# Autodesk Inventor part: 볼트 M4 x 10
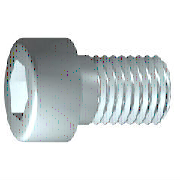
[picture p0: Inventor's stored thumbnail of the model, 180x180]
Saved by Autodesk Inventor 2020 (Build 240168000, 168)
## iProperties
Created: 2016-04
Part Number: 볼트 M4 x 10
Material: 강철, 연강
Description: 6각머리 태핑 나사
Document SubType Name: Modeling
Standard: KS B 1003
Designer: mdu
Standards Organization: KS
Language: ko-KR
Size Designation: M 4 x 10
Categories: <MemberInstance><Categories><Category DisplayName="조임쇠" InternalName="e4da775c-781d-43d5-af7c-5136215cf5a6" Mnemonic="FSTN"><Category DisplayName="볼트" InternalN
Density: 7.86 g/cm^3
Mass: 2.0371 g
Surface Area: 3.0572 cm^2
Volume: 0.259174 cm^3
Appearance: 강철
IsCustomPart: 0
Author: mdu
Revision Number: 1
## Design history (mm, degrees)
sketch "스케치1"
  geometry: L1 (-1, 0)-(10, 0); L2 (10, 0)-(10, 2); L3 (10, 2)-(1.75, 2); L4 (1.75, 2)-(1.32, 2); L5 (1.32, 2)-(0, 2); L6 (0, 2)-(0, 3.5); L7 (0, 3.5)-(-4, 3.5); L8 (-4, 3.5)-(-4, 1.732); L9 (-4, 1.732)-(-2, 1.732); L10 (-2, 1.732)-(-1, 0); L11 (-6.8, 0)-(12.8, 0) reference; L12 (0, -0.7)-(0, 4.2) reference; L13 (1.75, 2)-(0, 2)
  constraints: 22 end point, 6 parallel, 2 collinear, 2 perpendicular, 1 horizontal, 1 point on line
  dimensions: "d1" = 8.25 distance from line of L3.end L2 (= GEL); "d2" = 0.42952 distance of L4.end L3.end (computed from GAL); "d3" = 4 distance between parallel lines of L8 L6 (= KOH); "d4" = 2 distance of L8.end L9.end (= INTI); "d5" = 60 deg angle of L10 L1; "d6" = 4 diameter of L3 L1 (= GD); "d7" = 4 diameter of L5 L1 (= BDM); "d8" = 3.4641 diameter of L9 L1 (= 1.1547 x SW); "d9" = 7 diameter of L7 L1 (= KOD); "d26" = 10 distance between parallel lines of L12 L2 (= NLG)
revolve "본체" sketch "스케치1" stored, may be unused: angle "d10" = 90 deg
sketch "스케치2"
  geometry: L1 (0, -4.9)-(0, 4.9) reference; L2 (-4.9, 0)-(4.9, 0) reference; L3 (1.732, 0)-(0.866, -1.5); L4 (0.866, -1.5)-(-0.866, -1.5); L5 (-0.866, -1.5)-(-1.732, 0); L6 (-1.732, 0)-(-0.866, 1.5); L7 (-0.866, 1.5)-(0.866, 1.5); L8 (0.866, 1.5)-(1.732, 0); 2 further points
  constraints: 12 end point, 1 coincident, 1 horizontal alignment, 1 point on line, 12 other
extrude "슬롯" join sketch "스케치2" stored distance "d11" = 10; taper "d12" = 0 deg
workplane "Work Plane1"
fillet "Fillet2" dims "d30" = 0.1 (= R)
body "Solid1"
fillet "모깎기1" dims "d17" = 0.4 (= RR)
feature "스레드" dims "d13" = 8.25 (= GEL), "d14" = 0
chamfer "모따기1" distance "d15" = 0.42941 (= -0.5 x SPD + 0.5 x GD); stored, may be unused: second distance "d16" = 0.42941 (= GUL), angle "d27" = 45 deg
other parameters: "GD" = 4 (= NND) [user parameter; used in 2 equation terms], "NLG" = 10 [user parameter; used in 1 equation term], "GEL" = 8.25 [user parameter; used in 2 equation terms], "KOD" = 7 [user parameter; used in 1 equation term], "KOH" = 4 [user parameter; used in 1 equation term], "INTI" = 2 [user parameter; used in 1 equation term], "GAL" = 0.42941 (= 0.61345 x PTC) [user parameter; used in 1 equation term], "GUL" = 0.42941 (= 0.61345 x PTC) [user parameter; used in 1 equation term], "BDM" = 4 (= NND) [user parameter; used in 1 equation term], "SW" = 3 [user parameter; used in 2 equation terms], "RR" = 0.4 [user parameter; used in 1 equation term], "SPD" = 3.14117 (= NND - 1.2269 x PTC) [user parameter; used in 1 equation term], "d19" = 0, "d28" = 0, "d29" = 0, "R" = 0.1 [user parameter; used in 1 equation term], "PHH" = 0.2 [user parameter], "GD1" = 3.14117 (= THREADDIA - 1.2269 x PTC) [user parameter], "THREADDIA" = 4 [user parameter; used in 1 equation term], "FAWI" = 45 deg [user parameter], "TPU" = 14.28571 (computed from PTC) [user parameter], "PTC" = 0.7 [user parameter; used in 5 equation terms], "NND" = 4 [user parameter; used in 3 equation terms], "TOA" = 30 deg [user parameter], "E0" = 3.465 (= 1.155 x SW) [user parameter]
